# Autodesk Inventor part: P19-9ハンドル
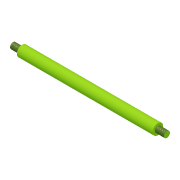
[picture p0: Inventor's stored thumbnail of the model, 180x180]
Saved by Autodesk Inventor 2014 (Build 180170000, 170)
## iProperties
Created: 2008-07
Part Number: P19-9ハンドル
Document SubType Name: Modeling
Designer: y-shimohigashi
Density: 1 g/cm^3
Stock Number: P19-9ハンドル
Material: 一般
Appearance: Green Meteorite
Author: y-shimohigashi
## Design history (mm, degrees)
sketch "スケッチ1"
  geometry: L1 (-102, 0)-(102, 0); L2 (-102, 0)-(-102, 4); L3 (-102, 4)-(-90, 4); L4 (-90, 4)-(-90, 7); L5 (-90, 7)-(90, 7); L6 (90, 7)-(90, 4); L7 (90, 4)-(102, 4); L8 (102, 4)-(102, 0); 2 further points
  constraints: 16 end point, 4 parallel, 3 collinear, 2 perpendicular, 1 coincident, 1 horizontal, 1 midpoint
  dimensions: "d0" = 7 distance between parallel lines of L1 L5; "d1" = 4 distance of L7.end L1.end; "d2" = 180 distance of L4.end L5.end; "d3" = 12 distance of L6.end L7.end
revolve "回転1" sketch "スケッチ1" stored, may be unused: angle "d4" = 90 deg
feature "ねじ1" dims "d5" = 10, "d6" = 0
feature "ねじ2" dims "d7" = 10, "d8" = 0
node "ソリッド1"
node "ソリッド ボディ"
node "サーフェス ボディ"
